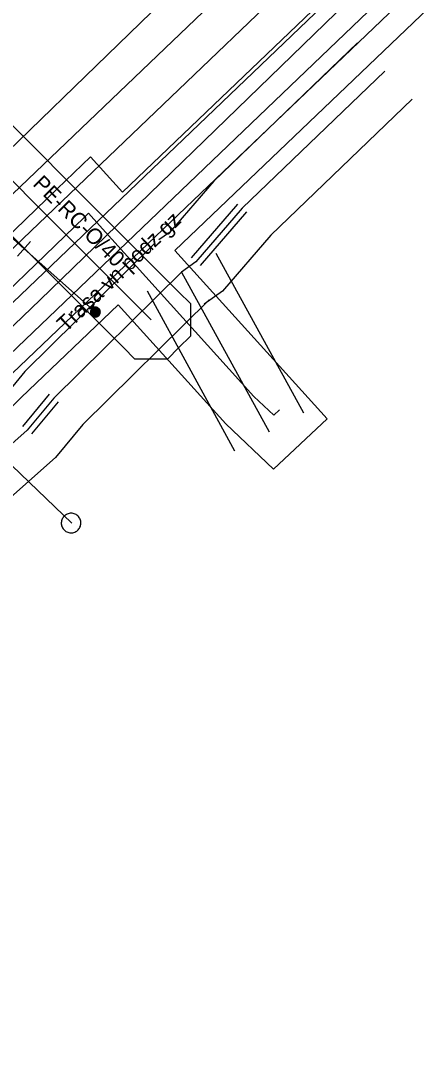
# Model space of a CAD drawing. Extents: x -762993 to -761845, y -975230 to -974501.
# Drawn here: x -762214.93 to -762204.67, y -974970.05 to -974943.8 of the extents above; entities that cross this region are included whole.
import ezdxf

# ---------------------------------------------------------------- set-up
doc = ezdxf.new("R2010")
doc.units = 0
for name, color, linetype in [('IS_CETIN_chranicka', 7, 'Continuous'), ('IS_CETIN_OP', 7, 'Continuous'), ('IS_CETIN_podzem metalika zam', 7, 'Continuous'), ('IS_CETIN_podzem optika zam', 7, 'Continuous'), ('IS_CEZ-D_anotace', 7, 'Continuous'), ('IS_CEZ-D_el vedeni NN podzem', 7, 'Continuous'), ('IS_CEZ-D_el vedeni VN podzem', 7, 'Continuous'), ('IS_CEZ-D_el vedeni VN podzem soubeh investice', 7, 'Continuous'), ('IS_CEZ-D_OP', 7, 'Continuous'), ('IS_DPmUL_OP', 7, 'Continuous'), ('IS_DPmUL_VO vedeni podzem', 7, 'Continuous'), ('IS_GASNET_plyn NTL anotace', 7, 'Continuous'), ('IS_GASNET_plyn NTL pripojky', 7, 'Continuous'), ('IS_GASNET_plyn OP', 7, 'Continuous'), ('IS_SCVK_vodovod pripojky', 7, 'Continuous'), ('IS_SCVK_vodovod privadec', 7, 'Continuous'), ('IS_SCVK_vodovod znaky', 7, 'Continuous'), ('IS_TPS_podzem metalika', 7, 'Continuous')]:
    doc.layers.add(name, color=color, linetype=linetype)

msp = doc.modelspace()

# ---------------------------------------------------------------- linework, layer by layer
at = {"layer": 'IS_CETIN_chranicka'}
for points in [[(-762210.574, -974949.842), (-762209.394, -974948.472)], [(-762210.346, -974950.038), (-762209.166, -974948.668)], [(-762214.875, -974954.134), (-762214.195, -974953.314)], [(-762214.645, -974954.326), (-762213.965, -974953.506)]]:
    msp.add_lwpolyline(points, dxfattribs=at)
at = {"layer": 'IS_CETIN_OP'}
for points in [[(-762206.343, -974944.359), (-762210.007, -974947.882), (-762211.137, -974949.193), (-762211.405, -974949.382)], [(-762204.957, -974945.801), (-762208.553, -974949.258), (-762209.783, -974950.687), (-762210.255, -974951.018)], [(-762211.533, -974949.489), (-762214.818, -974952.733), (-762215.481, -974953.533), (-762217.986, -974955.753), (-762221.653, -974959.239), (-762226.337, -974964.063)], [(-762209.953, -974949.719), (-762207.723, -974953.789)], [(-762211.707, -974950.681), (-762209.477, -974954.751)], [(-762210.127, -974950.911), (-762213.342, -974954.087), (-762214.039, -974954.927), (-762216.634, -974957.227), (-762220.247, -974960.661), (-762224.903, -974965.457)]]:
    msp.add_lwpolyline(points, dxfattribs=at)
at = {"layer": 'IS_CETIN_podzem metalika zam'}
msp.add_lwpolyline([(-762210.83, -974950.2), (-762208.6, -974954.27)], dxfattribs=at)
at = {"layer": 'IS_CETIN_podzem optika zam'}
for points in [[(-762205.65, -974945.08), (-762209.28, -974948.57), (-762210.46, -974949.94), (-762210.83, -974950.2)], [(-762210.83, -974950.2), (-762214.08, -974953.41), (-762214.76, -974954.23), (-762217.31, -974956.49), (-762220.95, -974959.95), (-762225.62, -974964.76)]]:
    msp.add_lwpolyline(points, dxfattribs=at)
at = {"layer": 'IS_CEZ-D_el vedeni NN podzem'}
msp.add_lwpolyline([(-762208.334, -974953.71), (-762208.48, -974953.847), (-762208.988, -974953.368), (-762212.916, -974949.013), (-762213.196, -974948.702), (-762213.301, -974948.803), (-762216.542, -974951.927), (-762221.91, -974957.079), (-762222.456, -974958.155), (-762224.696, -974962.752), (-762226.947, -974964.881), (-762227.041, -974964.97), (-762223.906, -974968.281), (-762223.426, -974968.788), (-762223.572, -974968.926)], dxfattribs=at)
at = {"layer": 'IS_CEZ-D_el vedeni VN podzem'}
msp.add_lwpolyline([(-762178.94, -974917.38), (-762180.88, -974919.33), (-762183.85, -974922.18), (-762189.02, -974927.27), (-762191.6, -974929.28), (-762204.29, -974941.85), (-762215.61, -974952.68), (-762222.04, -974959.06), (-762225.71, -974962.96), (-762226.91, -974964.67), (-762236.89, -974974.42), (-762240.73, -974978.21), (-762245.09, -974982.81)], dxfattribs=at)
at = {"layer": 'IS_CEZ-D_el vedeni VN podzem soubeh investice'}
msp.add_lwpolyline([(-762246.655, -974985.018), (-762244.801, -974983.086), (-762240.444, -974978.49), (-762236.61, -974974.705), (-762226.604, -974964.93), (-762225.399, -974963.213), (-762221.753, -974959.339), (-762215.331, -974952.967), (-762204.011, -974942.137), (-762191.335, -974929.581), (-762188.756, -974927.571), (-762183.571, -974922.467), (-762180.6, -974919.615), (-762178.658, -974917.664), (-762169.2, -974908.366)], dxfattribs=at)
at = {"layer": 'IS_CEZ-D_OP'}
msp.add_line((-762207.122, -974953.944), (-762210.996, -974949.649), dxfattribs=at)
for points in [[(-762179.649, -974916.675), (-762181.581, -974918.616), (-762184.547, -974921.463), (-762189.68, -974926.517), (-762192.261, -974928.528), (-762204.988, -974941.133), (-762212.335, -974948.163)], [(-762178.231, -974918.085), (-762180.179, -974920.044), (-762183.153, -974922.897), (-762188.36, -974928.023), (-762190.939, -974930.032), (-762203.592, -974942.567), (-762210.996, -974949.649)], [(-762212.335, -974948.163), (-762213.144, -974947.265), (-762213.995, -974948.083), (-762217.235, -974951.206), (-762222.725, -974956.475), (-762223.351, -974957.71), (-762224.65, -974960.374)], [(-762212.441, -974951.032), (-762214.912, -974953.396), (-762221.323, -974959.758), (-762222.985, -974961.523)], [(-762207.122, -974953.944), (-762208.482, -974955.22), (-762209.703, -974954.068), (-762212.441, -974951.032)]]:
    msp.add_lwpolyline(points, dxfattribs=at)
at = {"layer": 'IS_DPmUL_OP'}
for p, q in [((-762228.861, -974961.348), (-762208.613, -974941.975)), ((-762227.465, -974962.78), (-762207.231, -974943.421))]:
    msp.add_line(p, q, dxfattribs=at)
at = {"layer": 'IS_DPmUL_VO vedeni podzem'}
msp.add_lwpolyline([(-762228.163, -974962.064), (-762207.922, -974942.698)], dxfattribs=at)
at = {"layer": 'IS_GASNET_plyn NTL pripojky'}
msp.add_lwpolyline([(-762218.08, -974944.94), (-762211.6, -974951.42)], dxfattribs=at)
at = {"layer": 'IS_GASNET_plyn OP'}
msp.add_lwpolyline([(-762217.666, -974943.94), (-762217.373, -974944.233), (-762210.893, -974950.713), (-762210.6, -974951.006), (-762210.6, -974951.834), (-762210.893, -974952.127), (-762211.186, -974952.42), (-762212.014, -974952.42), (-762212.307, -974952.127), (-762218.787, -974945.647), (-762219.08, -974945.354), (-762219.08, -974944.526), (-762218.787, -974944.233), (-762218.494, -974943.94)], close=True, dxfattribs=at)
at = {"layer": 'IS_SCVK_vodovod pripojky'}
msp.add_lwpolyline([(-762216.028, -974954.299), (-762213.626, -974956.595)], dxfattribs=at)
at = {"layer": 'IS_SCVK_vodovod privadec'}
for points in [[(-762201.113, -974933.408), (-762202.03, -974934.3), (-762216.385, -974948.217)], [(-762216.385, -974948.217), (-762214.841, -974949.611)], [(-762214.841, -974949.611), (-762213.022, -974951.219)]]:
    msp.add_lwpolyline(points, dxfattribs=at)
at = {"layer": 'IS_SCVK_vodovod znaky'}
for points in [[(-762214.676, -974949.424), (-762215.007, -974949.798)], [(-762213.148, -974951.219), (-762213.148, -974951.232), (-762213.146, -974951.245), (-762213.143, -974951.258), (-762213.138, -974951.27), (-762213.132, -974951.282), (-762213.125, -974951.293), (-762213.117, -974951.303), (-762213.107, -974951.313), (-762213.097, -974951.321), (-762213.086, -974951.328), (-762213.074, -974951.334), (-762213.062, -974951.339), (-762213.049, -974951.342), (-762213.036, -974951.344), (-762213.023, -974951.346), (-762213.01, -974951.345), (-762212.997, -974951.343), (-762212.984, -974951.34), (-762212.972, -974951.335), (-762212.96, -974951.329), (-762212.949, -974951.322), (-762212.939, -974951.314), (-762212.929, -974951.304), (-762212.921, -974951.294), (-762212.914, -974951.283), (-762212.908, -974951.271), (-762212.903, -974951.259), (-762212.9, -974951.246), (-762212.898, -974951.233), (-762212.896, -974951.22), (-762212.897, -974951.207), (-762212.899, -974951.194), (-762212.902, -974951.181), (-762212.907, -974951.169), (-762212.913, -974951.157), (-762212.92, -974951.146), (-762212.928, -974951.136), (-762212.938, -974951.126), (-762212.948, -974951.118), (-762212.959, -974951.111), (-762212.971, -974951.105), (-762212.983, -974951.1), (-762212.996, -974951.097), (-762213.009, -974951.095), (-762213.022, -974951.094), (-762213.035, -974951.094), (-762213.048, -974951.096), (-762213.061, -974951.099), (-762213.073, -974951.104), (-762213.085, -974951.11), (-762213.096, -974951.117), (-762213.106, -974951.125), (-762213.116, -974951.135), (-762213.124, -974951.145), (-762213.131, -974951.156), (-762213.137, -974951.168), (-762213.142, -974951.18), (-762213.145, -974951.193), (-762213.147, -974951.206), (-762213.148, -974951.219)], [(-762213.128, -974951.219), (-762213.129, -974951.23), (-762213.127, -974951.241), (-762213.124, -974951.252), (-762213.12, -974951.262), (-762213.115, -974951.272), (-762213.109, -974951.281), (-762213.102, -974951.29), (-762213.094, -974951.298), (-762213.085, -974951.305), (-762213.076, -974951.311), (-762213.066, -974951.316), (-762213.056, -974951.32), (-762213.045, -974951.323), (-762213.034, -974951.326), (-762213.023, -974951.326), (-762213.012, -974951.326), (-762213.001, -974951.324), (-762212.99, -974951.321), (-762212.98, -974951.317), (-762212.97, -974951.312), (-762212.961, -974951.306), (-762212.952, -974951.299), (-762212.944, -974951.291), (-762212.937, -974951.282), (-762212.931, -974951.273), (-762212.926, -974951.263), (-762212.922, -974951.253), (-762212.919, -974951.242), (-762212.917, -974951.231), (-762212.916, -974951.22), (-762212.916, -974951.209), (-762212.918, -974951.198), (-762212.921, -974951.187), (-762212.925, -974951.177), (-762212.93, -974951.167), (-762212.936, -974951.158), (-762212.943, -974951.149), (-762212.951, -974951.141), (-762212.96, -974951.134), (-762212.969, -974951.128), (-762212.979, -974951.123), (-762212.989, -974951.119), (-762213, -974951.116), (-762213.011, -974951.114), (-762213.022, -974951.114), (-762213.033, -974951.113), (-762213.044, -974951.115), (-762213.055, -974951.118), (-762213.065, -974951.122), (-762213.075, -974951.127), (-762213.084, -974951.133), (-762213.093, -974951.14), (-762213.101, -974951.148), (-762213.108, -974951.157), (-762213.114, -974951.166), (-762213.119, -974951.176), (-762213.123, -974951.186), (-762213.126, -974951.197), (-762213.128, -974951.208), (-762213.128, -974951.219)], [(-762213.109, -974951.219), (-762213.109, -974951.228), (-762213.108, -974951.237), (-762213.105, -974951.246), (-762213.102, -974951.254), (-762213.098, -974951.262), (-762213.093, -974951.27), (-762213.087, -974951.277), (-762213.081, -974951.283), (-762213.074, -974951.289), (-762213.066, -974951.294), (-762213.058, -974951.298), (-762213.05, -974951.301), (-762213.041, -974951.304), (-762213.032, -974951.305), (-762213.023, -974951.307), (-762213.014, -974951.306), (-762213.005, -974951.305), (-762212.996, -974951.302), (-762212.988, -974951.299), (-762212.98, -974951.295), (-762212.972, -974951.29), (-762212.965, -974951.284), (-762212.959, -974951.278), (-762212.953, -974951.271), (-762212.948, -974951.263), (-762212.944, -974951.255), (-762212.941, -974951.247), (-762212.938, -974951.238), (-762212.937, -974951.229), (-762212.934, -974951.22), (-762212.936, -974951.211), (-762212.937, -974951.202), (-762212.94, -974951.193), (-762212.943, -974951.185), (-762212.947, -974951.177), (-762212.952, -974951.169), (-762212.958, -974951.162), (-762212.964, -974951.156), (-762212.971, -974951.15), (-762212.979, -974951.145), (-762212.987, -974951.141), (-762212.995, -974951.138), (-762213.004, -974951.135), (-762213.013, -974951.134), (-762213.022, -974951.133), (-762213.031, -974951.133), (-762213.04, -974951.134), (-762213.049, -974951.137), (-762213.057, -974951.14), (-762213.065, -974951.144), (-762213.073, -974951.149), (-762213.08, -974951.155), (-762213.086, -974951.161), (-762213.092, -974951.168), (-762213.097, -974951.176), (-762213.101, -974951.184), (-762213.104, -974951.192), (-762213.107, -974951.201), (-762213.108, -974951.21), (-762213.109, -974951.219)], [(-762213.089, -974951.219), (-762213.089, -974951.226), (-762213.088, -974951.233), (-762213.087, -974951.24), (-762213.084, -974951.246), (-762213.081, -974951.252), (-762213.077, -974951.258), (-762213.073, -974951.264), (-762213.068, -974951.269), (-762213.062, -974951.273), (-762213.056, -974951.277), (-762213.05, -974951.28), (-762213.044, -974951.283), (-762213.037, -974951.284), (-762213.03, -974951.287), (-762213.023, -974951.287), (-762213.016, -974951.287), (-762213.009, -974951.285), (-762213.002, -974951.284), (-762212.996, -974951.281), (-762212.989, -974951.278), (-762212.984, -974951.274), (-762212.978, -974951.27), (-762212.973, -974951.265), (-762212.969, -974951.259), (-762212.965, -974951.253), (-762212.962, -974951.247), (-762212.959, -974951.241), (-762212.957, -974951.234), (-762212.956, -974951.227), (-762212.955, -974951.22), (-762212.955, -974951.213), (-762212.956, -974951.206), (-762212.958, -974951.199), (-762212.961, -974951.193), (-762212.964, -974951.186), (-762212.968, -974951.181), (-762212.972, -974951.175), (-762212.977, -974951.17), (-762212.983, -974951.166), (-762212.988, -974951.162), (-762212.995, -974951.159), (-762213.001, -974951.156), (-762213.008, -974951.154), (-762213.015, -974951.153), (-762213.022, -974951.153), (-762213.029, -974951.153), (-762213.036, -974951.153), (-762213.043, -974951.155), (-762213.049, -974951.158), (-762213.055, -974951.161), (-762213.061, -974951.165), (-762213.067, -974951.169), (-762213.072, -974951.174), (-762213.076, -974951.18), (-762213.08, -974951.185), (-762213.083, -974951.192), (-762213.086, -974951.198), (-762213.087, -974951.205), (-762213.089, -974951.212), (-762213.089, -974951.219)], [(-762213.069, -974951.219), (-762213.069, -974951.224), (-762213.069, -974951.229), (-762213.068, -974951.234), (-762213.066, -974951.238), (-762213.064, -974951.243), (-762213.061, -974951.247), (-762213.058, -974951.25), (-762213.054, -974951.254), (-762213.051, -974951.257), (-762213.047, -974951.26), (-762213.042, -974951.262), (-762213.038, -974951.264), (-762213.033, -974951.265), (-762213.028, -974951.267), (-762213.023, -974951.267), (-762213.018, -974951.267), (-762213.013, -974951.266), (-762213.008, -974951.265), (-762213.004, -974951.263), (-762212.999, -974951.261), (-762212.995, -974951.258), (-762212.991, -974951.255), (-762212.988, -974951.251), (-762212.985, -974951.248), (-762212.982, -974951.244), (-762212.98, -974951.239), (-762212.978, -974951.235), (-762212.977, -974951.23), (-762212.976, -974951.225), (-762212.975, -974951.22), (-762212.975, -974951.215), (-762212.976, -974951.21), (-762212.977, -974951.205), (-762212.979, -974951.201), (-762212.981, -974951.196), (-762212.984, -974951.192), (-762212.987, -974951.188), (-762212.99, -974951.185), (-762212.994, -974951.182), (-762212.998, -974951.179), (-762213.003, -974951.177), (-762213.007, -974951.175), (-762213.012, -974951.174), (-762213.017, -974951.173), (-762213.022, -974951.173), (-762213.027, -974951.173), (-762213.032, -974951.174), (-762213.037, -974951.174), (-762213.041, -974951.176), (-762213.046, -974951.178), (-762213.05, -974951.181), (-762213.053, -974951.184), (-762213.057, -974951.187), (-762213.059, -974951.191), (-762213.063, -974951.195), (-762213.065, -974951.2), (-762213.067, -974951.204), (-762213.068, -974951.209), (-762213.069, -974951.214), (-762213.069, -974951.219)], [(-762213.049, -974951.219), (-762213.049, -974951.222), (-762213.05, -974951.225), (-762213.049, -974951.227), (-762213.048, -974951.23), (-762213.047, -974951.233), (-762213.045, -974951.235), (-762213.043, -974951.237), (-762213.041, -974951.239), (-762213.039, -974951.241), (-762213.037, -974951.243), (-762213.034, -974951.245), (-762213.031, -974951.246), (-762213.029, -974951.246), (-762213.026, -974951.247), (-762213.023, -974951.247), (-762213.02, -974951.247), (-762213.017, -974951.247), (-762213.014, -974951.246), (-762213.012, -974951.245), (-762213.009, -974951.244), (-762213.007, -974951.242), (-762213.004, -974951.24), (-762213.002, -974951.238), (-762213.001, -974951.236), (-762212.999, -974951.234), (-762212.998, -974951.231), (-762212.996, -974951.228), (-762212.996, -974951.226), (-762212.995, -974951.223), (-762212.994, -974951.22), (-762212.995, -974951.217), (-762212.995, -974951.214), (-762212.996, -974951.211), (-762212.997, -974951.209), (-762212.998, -974951.206), (-762213, -974951.204), (-762213.001, -974951.201), (-762213.003, -974951.199), (-762213.006, -974951.198), (-762213.008, -974951.196), (-762213.011, -974951.195), (-762213.013, -974951.194), (-762213.016, -974951.193), (-762213.019, -974951.193), (-762213.022, -974951.192), (-762213.025, -974951.193), (-762213.028, -974951.192), (-762213.03, -974951.194), (-762213.033, -974951.194), (-762213.036, -974951.195), (-762213.038, -974951.197), (-762213.04, -974951.198), (-762213.042, -974951.2), (-762213.044, -974951.203), (-762213.046, -974951.205), (-762213.047, -974951.208), (-762213.048, -974951.21), (-762213.049, -974951.213), (-762213.049, -974951.216), (-762213.049, -974951.219)], [(-762213.03, -974951.219), (-762213.03, -974951.221), (-762213.03, -974951.221), (-762213.029, -974951.221), (-762213.029, -974951.223), (-762213.03, -974951.224), (-762213.028, -974951.224), (-762213.028, -974951.224), (-762213.028, -974951.226), (-762213.028, -974951.226), (-762213.027, -974951.227), (-762213.025, -974951.227), (-762213.025, -974951.227), (-762213.025, -974951.228), (-762213.023, -974951.228), (-762213.023, -974951.228), (-762213.022, -974951.228), (-762213.021, -974951.228), (-762213.021, -974951.227), (-762213.02, -974951.227), (-762213.018, -974951.227), (-762213.018, -974951.226), (-762213.018, -974951.226), (-762213.017, -974951.225), (-762213.017, -974951.225), (-762213.015, -974951.224), (-762213.015, -974951.223), (-762213.014, -974951.222), (-762213.014, -974951.222), (-762213.014, -974951.221), (-762213.014, -974951.22), (-762213.014, -974951.219), (-762213.014, -974951.218), (-762213.014, -974951.218), (-762213.015, -974951.217), (-762213.015, -974951.216), (-762213.016, -974951.215), (-762213.016, -974951.215), (-762213.017, -974951.214), (-762213.017, -974951.214), (-762213.018, -974951.213), (-762213.019, -974951.213), (-762213.02, -974951.212), (-762213.02, -974951.212), (-762213.021, -974951.212), (-762213.022, -974951.212), (-762213.023, -974951.212), (-762213.024, -974951.212), (-762213.024, -974951.212), (-762213.025, -974951.213), (-762213.026, -974951.212), (-762213.027, -974951.214), (-762213.027, -974951.214), (-762213.028, -974951.214), (-762213.028, -974951.214), (-762213.029, -974951.216), (-762213.029, -974951.217), (-762213.029, -974951.218), (-762213.03, -974951.218), (-762213.03, -974951.219), (-762213.03, -974951.219)], [(-762213.806, -974956.407), (-762213.824, -974956.424)], [(-762213.806, -974956.407), (-762213.824, -974956.424)], [(-762213.785, -974956.39), (-762213.806, -974956.407)], [(-762213.785, -974956.39), (-762213.806, -974956.407)], [(-762213.763, -974956.376), (-762213.785, -974956.39)], [(-762213.763, -974956.376), (-762213.785, -974956.39)], [(-762213.74, -974956.365), (-762213.763, -974956.376)], [(-762213.74, -974956.365), (-762213.763, -974956.376)], [(-762213.715, -974956.356), (-762213.74, -974956.365)], [(-762213.715, -974956.356), (-762213.74, -974956.365)], [(-762213.689, -974956.349), (-762213.715, -974956.356)], [(-762213.689, -974956.349), (-762213.715, -974956.356)], [(-762213.664, -974956.346), (-762213.689, -974956.349)], [(-762213.664, -974956.346), (-762213.689, -974956.349)], [(-762213.638, -974956.345), (-762213.664, -974956.346)], [(-762213.638, -974956.345), (-762213.664, -974956.346)], [(-762213.611, -974956.347), (-762213.638, -974956.345)], [(-762213.611, -974956.347), (-762213.638, -974956.345)], [(-762213.585, -974956.351), (-762213.611, -974956.347)], [(-762213.585, -974956.351), (-762213.611, -974956.347)], [(-762213.56, -974956.359), (-762213.585, -974956.351)], [(-762213.56, -974956.359), (-762213.585, -974956.351)], [(-762213.537, -974956.369), (-762213.56, -974956.359)], [(-762213.537, -974956.369), (-762213.56, -974956.359)], [(-762213.513, -974956.381), (-762213.537, -974956.369)], [(-762213.513, -974956.381), (-762213.537, -974956.369)], [(-762213.492, -974956.396), (-762213.513, -974956.381)], [(-762213.492, -974956.396), (-762213.513, -974956.381)], [(-762213.471, -974956.413), (-762213.492, -974956.396)], [(-762213.471, -974956.413), (-762213.492, -974956.396)], [(-762213.89, -974956.564), (-762213.892, -974956.59)], [(-762213.89, -974956.564), (-762213.892, -974956.59)], [(-762213.892, -974956.59), (-762213.891, -974956.617)], [(-762213.892, -974956.59), (-762213.891, -974956.617)], [(-762213.891, -974956.617), (-762213.888, -974956.643)], [(-762213.891, -974956.617), (-762213.888, -974956.643)], [(-762213.885, -974956.538), (-762213.89, -974956.564)], [(-762213.885, -974956.538), (-762213.89, -974956.564)], [(-762213.888, -974956.643), (-762213.882, -974956.668)], [(-762213.888, -974956.643), (-762213.882, -974956.668)], [(-762213.878, -974956.513), (-762213.885, -974956.538)], [(-762213.878, -974956.513), (-762213.885, -974956.538)], [(-762213.882, -974956.668), (-762213.872, -974956.692)], [(-762213.882, -974956.668), (-762213.872, -974956.692)], [(-762213.868, -974956.489), (-762213.878, -974956.513)], [(-762213.868, -974956.489), (-762213.878, -974956.513)], [(-762213.856, -974956.466), (-762213.868, -974956.489)], [(-762213.856, -974956.466), (-762213.868, -974956.489)], [(-762213.841, -974956.444), (-762213.856, -974956.466)], [(-762213.841, -974956.444), (-762213.856, -974956.466)], [(-762213.824, -974956.424), (-762213.841, -974956.444)], [(-762213.824, -974956.424), (-762213.841, -974956.444)], [(-762213.453, -974956.432), (-762213.471, -974956.413)], [(-762213.453, -974956.432), (-762213.471, -974956.413)], [(-762213.437, -974956.452), (-762213.453, -974956.432)], [(-762213.437, -974956.452), (-762213.453, -974956.432)], [(-762213.424, -974956.474), (-762213.437, -974956.452)], [(-762213.424, -974956.474), (-762213.437, -974956.452)], [(-762213.412, -974956.498), (-762213.424, -974956.474)], [(-762213.412, -974956.498), (-762213.424, -974956.474)], [(-762213.403, -974956.523), (-762213.412, -974956.498)], [(-762213.403, -974956.523), (-762213.412, -974956.498)], [(-762213.406, -974956.677), (-762213.399, -974956.652)], [(-762213.406, -974956.677), (-762213.399, -974956.652)], [(-762213.397, -974956.548), (-762213.403, -974956.523)], [(-762213.397, -974956.548), (-762213.403, -974956.523)], [(-762213.399, -974956.652), (-762213.395, -974956.626)], [(-762213.399, -974956.652), (-762213.395, -974956.626)], [(-762213.394, -974956.574), (-762213.397, -974956.548)], [(-762213.394, -974956.574), (-762213.397, -974956.548)], [(-762213.393, -974956.6), (-762213.394, -974956.574)], [(-762213.393, -974956.6), (-762213.394, -974956.574)], [(-762213.395, -974956.626), (-762213.393, -974956.6)], [(-762213.395, -974956.626), (-762213.393, -974956.6)], [(-762213.872, -974956.692), (-762213.861, -974956.716)], [(-762213.872, -974956.692), (-762213.861, -974956.716)], [(-762213.861, -974956.716), (-762213.846, -974956.738)], [(-762213.861, -974956.716), (-762213.846, -974956.738)], [(-762213.846, -974956.738), (-762213.831, -974956.758)], [(-762213.846, -974956.738), (-762213.831, -974956.758)], [(-762213.831, -974956.758), (-762213.813, -974956.777)], [(-762213.831, -974956.758), (-762213.813, -974956.777)], [(-762213.813, -974956.777), (-762213.793, -974956.794)], [(-762213.813, -974956.777), (-762213.793, -974956.794)], [(-762213.793, -974956.794), (-762213.772, -974956.809)], [(-762213.793, -974956.794), (-762213.772, -974956.809)], [(-762213.772, -974956.809), (-762213.748, -974956.822)], [(-762213.772, -974956.809), (-762213.748, -974956.822)], [(-762213.748, -974956.822), (-762213.724, -974956.831)], [(-762213.748, -974956.822), (-762213.724, -974956.831)], [(-762213.724, -974956.831), (-762213.699, -974956.839)], [(-762213.724, -974956.831), (-762213.699, -974956.839)], [(-762213.699, -974956.839), (-762213.674, -974956.843)], [(-762213.699, -974956.839), (-762213.674, -974956.843)], [(-762213.674, -974956.843), (-762213.647, -974956.845)], [(-762213.674, -974956.843), (-762213.647, -974956.845)], [(-762213.647, -974956.845), (-762213.621, -974956.844)], [(-762213.647, -974956.845), (-762213.621, -974956.844)], [(-762213.621, -974956.844), (-762213.595, -974956.841)], [(-762213.621, -974956.844), (-762213.595, -974956.841)], [(-762213.595, -974956.841), (-762213.569, -974956.834)], [(-762213.595, -974956.841), (-762213.569, -974956.834)], [(-762213.569, -974956.834), (-762213.545, -974956.825)], [(-762213.569, -974956.834), (-762213.545, -974956.825)], [(-762213.545, -974956.825), (-762213.521, -974956.814)], [(-762213.545, -974956.825), (-762213.521, -974956.814)], [(-762213.521, -974956.814), (-762213.499, -974956.8)], [(-762213.521, -974956.814), (-762213.499, -974956.8)], [(-762213.499, -974956.8), (-762213.479, -974956.784)], [(-762213.499, -974956.8), (-762213.479, -974956.784)], [(-762213.479, -974956.784), (-762213.459, -974956.766)], [(-762213.479, -974956.784), (-762213.459, -974956.766)], [(-762213.459, -974956.766), (-762213.443, -974956.746)], [(-762213.459, -974956.766), (-762213.443, -974956.746)], [(-762213.443, -974956.746), (-762213.427, -974956.724)], [(-762213.443, -974956.746), (-762213.427, -974956.724)], [(-762213.427, -974956.724), (-762213.416, -974956.701)], [(-762213.427, -974956.724), (-762213.416, -974956.701)], [(-762213.416, -974956.701), (-762213.406, -974956.677)], [(-762213.416, -974956.701), (-762213.406, -974956.677)]]:
    msp.add_lwpolyline(points, dxfattribs=at)
at = {"layer": 'IS_TPS_podzem metalika'}
msp.add_lwpolyline([(-762172.29, -974910.28), (-762185.23, -974922.87), (-762190.46, -974927.24), (-762198, -974934.74), (-762201.39, -974938.15), (-762206.9, -974943.61), (-762214.43, -974950.91), (-762220.21, -974956.46), (-762222.55, -974958.76), (-762223.79, -974960.27), (-762224.33, -974962.55), (-762233.162, -974970.759), (-762240.486, -974977.956), (-762246.238, -974984.004)], dxfattribs=at)

# ---------------------------------------------------------------- texts
at = {"layer": 'IS_CEZ-D_anotace'}
msp.add_text('Trasa vn podz gz', height=0.4, rotation=43.7327, dxfattribs=at).set_placement((-762213.769, -974951.75))
at = {"layer": 'IS_GASNET_plyn NTL anotace'}
msp.add_text('PE-RC-O/40', height=0.4, rotation=315, dxfattribs=at).set_placement((-762214.64, -974947.98))

doc.saveas('drawing.dxf')
